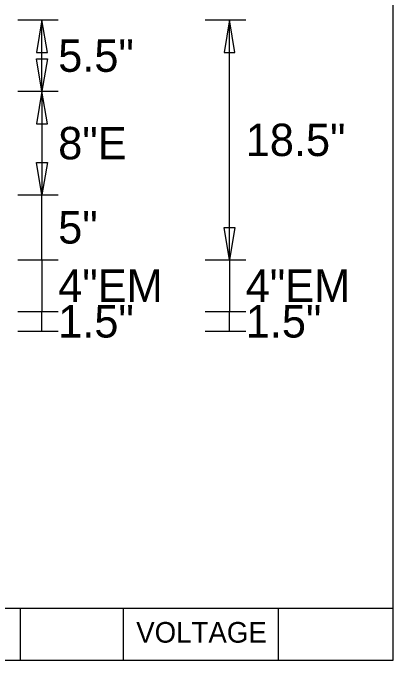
# Model space of a CAD drawing. Extents: x -998.8 to -961.2, y -2311.8 to -2287.8.
# Drawn here: x -982.592 to -980.149, y -2294.158 to -2289.997 of the extents above; entities that cross this region are included whole.
import ezdxf

# ---------------------------------------------------------------- set-up
doc = ezdxf.new("R2010")
doc.units = 0
for name, color, linetype in [('GSDims', 7, 'Continuous'), ('SheetLinesMisc2_dp', 7, 'Continuous'), ('TextMinor', 7, 'Continuous')]:
    doc.layers.add(name, color=color, linetype=linetype)

msp = doc.modelspace()

# ---------------------------------------------------------------- linework, layer by layer
at = {"layer": 'GSDims'}
for p, q in [((-982.5615, -2290.0424), (-982.3011, -2290.0424)), ((-982.4053, -2290.5009), (-982.4053, -2290.0424)), ((-981.3563, -2290.0424), (-981.0959, -2290.0424)), ((-981.2001, -2291.5841), (-981.2001, -2290.0424)), ((-982.5615, -2290.5009), (-982.3011, -2290.5009)), ((-982.5615, -2290.5009), (-982.3011, -2290.5009)), ((-982.4053, -2290.5009), (-982.4053, -2291.1675)), ((-982.5615, -2291.1675), (-982.3011, -2291.1675)), ((-982.5615, -2291.1675), (-982.3011, -2291.1675)), ((-982.4053, -2291.5841), (-982.4053, -2291.1675)), ((-982.5615, -2291.5841), (-982.3011, -2291.5841)), ((-982.5615, -2291.5841), (-982.3011, -2291.5841)), ((-982.4053, -2291.5841), (-982.4053, -2291.9174)), ((-981.3563, -2291.5841), (-981.0959, -2291.5841)), ((-981.3563, -2291.5841), (-981.0959, -2291.5841)), ((-981.2001, -2291.5841), (-981.2001, -2291.9175)), ((-982.5615, -2291.9174), (-982.3011, -2291.9174)), ((-982.5615, -2291.9174), (-982.3011, -2291.9174)), ((-982.4053, -2292.0425), (-982.4053, -2291.9174)), ((-981.3563, -2291.9175), (-981.0959, -2291.9175)), ((-981.3563, -2291.9175), (-981.0959, -2291.9175)), ((-981.2001, -2292.0425), (-981.2001, -2291.9175)), ((-982.5615, -2292.0425), (-982.3011, -2292.0425)), ((-981.3563, -2292.0425), (-981.0959, -2292.0425))]:
    msp.add_line(p, q, dxfattribs=at)
for points in [[(-982.4053, -2290.0424), (-982.44, -2290.2508), (-982.3706, -2290.2508)], [(-981.2001, -2290.0424), (-981.2348, -2290.2508), (-981.1653, -2290.2508)], [(-982.4053, -2290.5009), (-982.44, -2290.2925), (-982.3706, -2290.2925)], [(-982.4053, -2290.5009), (-982.44, -2290.7092), (-982.3706, -2290.7092)], [(-982.4053, -2291.1675), (-982.44, -2290.9592), (-982.3706, -2290.9592)], [(-981.2001, -2291.5841), (-981.2348, -2291.3758), (-981.1653, -2291.3758)]]:
    msp.add_lwpolyline(points, close=True, dxfattribs=at)
at = {"layer": 'SheetLinesMisc2_dp'}
for p, q in [((-980.149, -2294.1578), (-980.149, -2287.9271)), ((-992.9402, -2293.8239), (-980.149, -2293.8239)), ((-982.5456, -2293.8239), (-982.5456, -2294.1578)), ((-981.8839, -2293.8239), (-981.8839, -2294.1578)), ((-980.8876, -2293.8239), (-980.8876, -2294.1578)), ((-992.9402, -2294.1578), (-980.149, -2294.1578))]:
    msp.add_line(p, q, dxfattribs=at)

# ---------------------------------------------------------------- texts
at = {"layer": 'GSDims'}
for s, p in [('5.5"', (-982.3011, -2290.3758)), ('18.5"', (-981.0959, -2290.9174)), ('8"E', (-982.3011, -2290.9384)), ('5"', (-982.3011, -2291.48)), ('4"EM', (-982.3011, -2291.8549)), ('4"EM', (-981.0959, -2291.855)), ('1.5"', (-982.3011, -2292.0841)), ('1.5"', (-981.0959, -2292.0841))]:
    msp.add_text(s, height=0.20833, dxfattribs=at).set_placement(p)
at = {"layer": 'TextMinor'}
msp.add_text('VOLTAGE', height=0.13286, dxfattribs=at).set_placement((-981.7997, -2294.046))

doc.saveas('drawing.dxf')
